Omron CX-Programmer project NuevoProyecto (CX-Programmer 9.50)

# PLC NewPLC1: CQM1 CPU21

## Global symbols (name address type ; comment)
DM0 CHANNEL  ; 0
TIM002 BOOL  ; T2
TIM003 BOOL  ; T3
TIM004 BOOL  ; T4
TIM005 BOOL  ; T5
TIM006 BOOL  ; T6
TIM007 BOOL  ; T7
TIM008 BOOL  ; T8

## Program P10_2 (no task)
Local symbols
EV1 100.04 BOOL  ; EV1=X6·Pm'
EV2 100.05 BOOL  ; EV2=X13·Pm'
EVA 100.00 BOOL  ; EVA=(X1+X10)·Pm'
EVB 100.01 BOOL  ; EVB=(X2+X9)Pm'
EVC 100.02 BOOL  ; EVC=X3·Pm'
EVD 100.03 BOOL  ; EVD=X8·Pm'
Etapa_0 10.00 BOOL
Etapa_1 10.01 BOOL
Etapa_10 10.10 BOOL
Etapa_11 10.11 BOOL
Etapa_12 10.12 BOOL
Etapa_13 10.13 BOOL
Etapa_14 10.14 BOOL
Etapa_2 10.02 BOOL
Etapa_3 10.03 BOOL
Etapa_4 10.04 BOOL
Etapa_5 10.05 BOOL
Etapa_6 10.06 BOOL
Etapa_7 10.07 BOOL
Etapa_8 10.08 BOOL
Etapa_9 10.09 BOOL
FC1 0.04 BOOL  ; Final carrera 1 (CNA)
FC2 0.05 BOOL  ; Final carrera 2 (CNA)
FC3 0.06 BOOL  ; Final carrera 3 (CNA)
FC4 0.07 BOOL  ; Final carrera 4 (CNA)
KCD 100.06 BOOL  ; KCD=(X1+X2+X3+X4)·Pm'
KCI 100.07 BOOL  ; KCI=(X8+X9+X10+X11)·Pm'
KV1D 101.00 BOOL  ; KV1D=X5·Pm'
KV1I 101.01 BOOL  ; KV1I=X7·Pm'
KV2D 101.02 BOOL  ; KV2D=X14·Pm'
KV2I 101.03 BOOL  ; KV2I=X12·Pm'
P 0.02 BOOL  ; Pulsador de paro (CNC)
Pm 15.00 BOOL  ; Pm=P·X0'+Pm·R'
R 0.03 BOOL  ; Pulsador de rearme (CNA)
m1 0.00 BOOL  ; Pulsador de marcha mezcla 1 (CNA)
m2 0.01 BOOL  ; Pulsador de marcha mezcla 2 (CNA)

### Section Sección1_Etapa_0

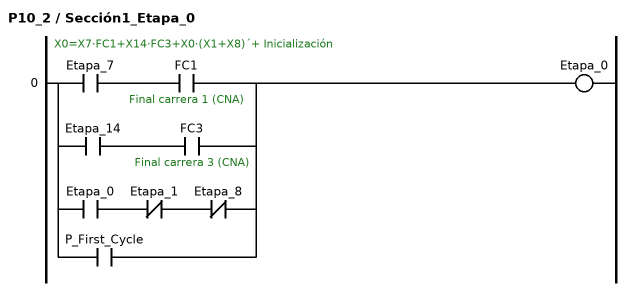
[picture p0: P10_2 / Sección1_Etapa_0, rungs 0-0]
; rung 0: X0=X7·FC1+X14·FC3+X0·(X1+X8)´+ Inicialización
LD Etapa_7
AND FC1  ; Final carrera 1 (CNA)
LD Etapa_14
AND FC3  ; Final carrera 3 (CNA)
ORLD
LD Etapa_0
ANDNOT Etapa_1
ANDNOT Etapa_8
ORLD
OR P_First_Cycle
OUT Etapa_0

### Section Sección2_Mezcla_1_Etapas_1_a_7

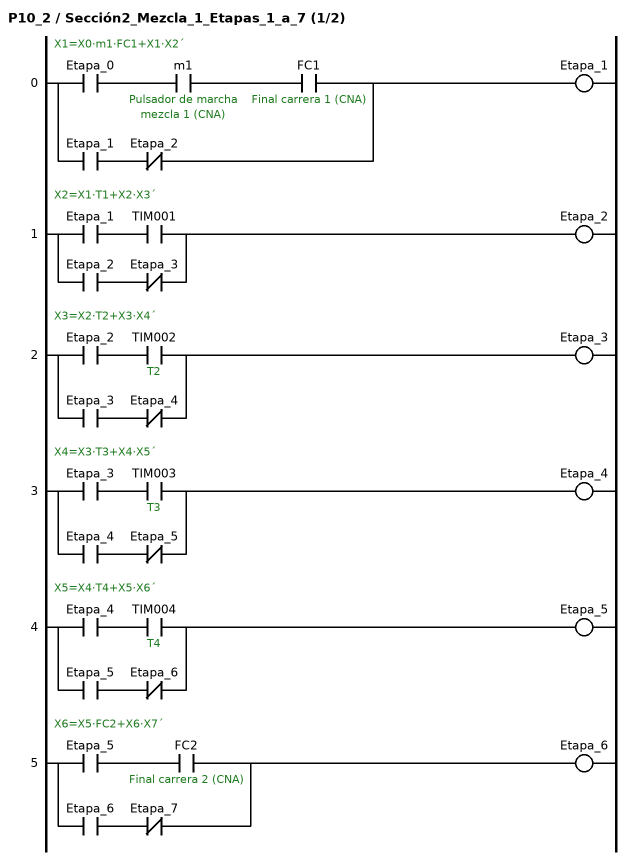
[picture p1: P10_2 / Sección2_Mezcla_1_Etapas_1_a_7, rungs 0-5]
; rung 0: X1=X0·m1·FC1+X1·X2´
LD Etapa_0
AND m1  ; Pulsador de marcha mezcla 1 (CNA)
AND FC1  ; Final carrera 1 (CNA)
LD Etapa_1
ANDNOT Etapa_2
ORLD
OUT Etapa_1
; rung 1: X2=X1·T1+X2·X3´
LD Etapa_1
AND TIM001
LD Etapa_2
ANDNOT Etapa_3
ORLD
OUT Etapa_2
; rung 2: X3=X2·T2+X3·X4´
LD Etapa_2
AND TIM002  ; T2
LD Etapa_3
ANDNOT Etapa_4
ORLD
OUT Etapa_3
; rung 3: X4=X3·T3+X4·X5´
LD Etapa_3
AND TIM003  ; T3
LD Etapa_4
ANDNOT Etapa_5
ORLD
OUT Etapa_4
; rung 4: X5=X4·T4+X5·X6´
LD Etapa_4
AND TIM004  ; T4
LD Etapa_5
ANDNOT Etapa_6
ORLD
OUT Etapa_5
; rung 5: X6=X5·FC2+X6·X7´
LD Etapa_5
AND FC2  ; Final carrera 2 (CNA)
LD Etapa_6
ANDNOT Etapa_7
ORLD
OUT Etapa_6

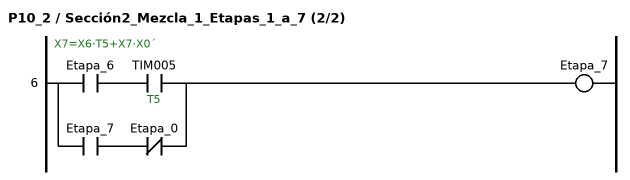
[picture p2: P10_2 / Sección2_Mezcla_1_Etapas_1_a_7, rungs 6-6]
; rung 6: X7=X6·T5+X7·X0´
LD Etapa_6
AND TIM005  ; T5
LD Etapa_7
ANDNOT Etapa_0
ORLD
OUT Etapa_7

### Section Sección3_Mezcla_2_Etapas_8_a_14

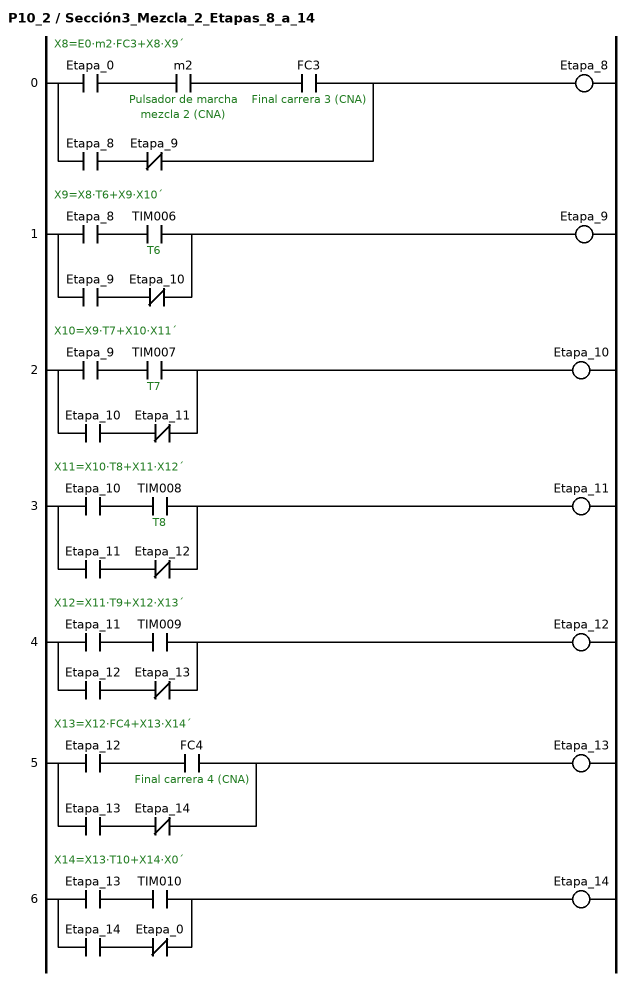
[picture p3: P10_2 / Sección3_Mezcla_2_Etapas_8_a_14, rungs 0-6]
; rung 0: X8=E0·m2·FC3+X8·X9´
LD Etapa_0
AND m2  ; Pulsador de marcha mezcla 2 (CNA)
AND FC3  ; Final carrera 3 (CNA)
LD Etapa_8
ANDNOT Etapa_9
ORLD
OUT Etapa_8
; rung 1: X9=X8·T6+X9·X10´
LD Etapa_8
AND TIM006  ; T6
LD Etapa_9
ANDNOT Etapa_10
ORLD
OUT Etapa_9
; rung 2: X10=X9·T7+X10·X11´
LD Etapa_9
AND TIM007  ; T7
LD Etapa_10
ANDNOT Etapa_11
ORLD
OUT Etapa_10
; rung 3: X11=X10·T8+X11·X12´
LD Etapa_10
AND TIM008  ; T8
LD Etapa_11
ANDNOT Etapa_12
ORLD
OUT Etapa_11
; rung 4: X12=X11·T9+X12·X13´
LD Etapa_11
AND TIM009
LD Etapa_12
ANDNOT Etapa_13
ORLD
OUT Etapa_12
; rung 5: X13=X12·FC4+X13·X14´
LD Etapa_12
AND FC4  ; Final carrera 4 (CNA)
LD Etapa_13
ANDNOT Etapa_14
ORLD
OUT Etapa_13
; rung 6: X14=X13·T10+X14·X0´
LD Etapa_13
AND TIM010
LD Etapa_14
ANDNOT Etapa_0
ORLD
OUT Etapa_14

### Section Sección4_Temporizadores
; Temporizadores

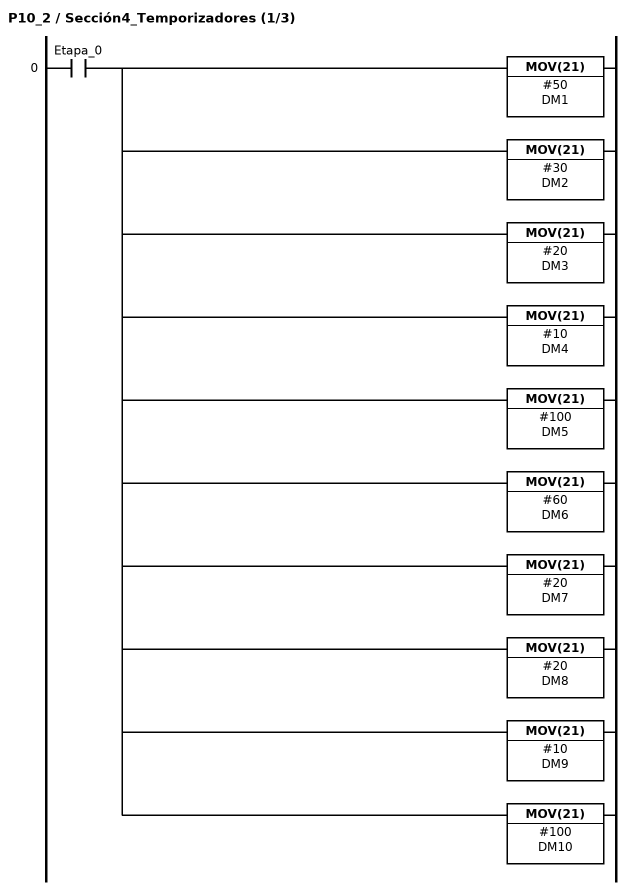
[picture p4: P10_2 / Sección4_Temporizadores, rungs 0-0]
; rung 0
LD Etapa_0
MOV(21) #50 DM1
MOV(21) #30 DM2
MOV(21) #20 DM3
MOV(21) #10 DM4
MOV(21) #100 DM5
MOV(21) #60 DM6
MOV(21) #20 DM7
MOV(21) #20 DM8
MOV(21) #10 DM9
MOV(21) #100 DM10

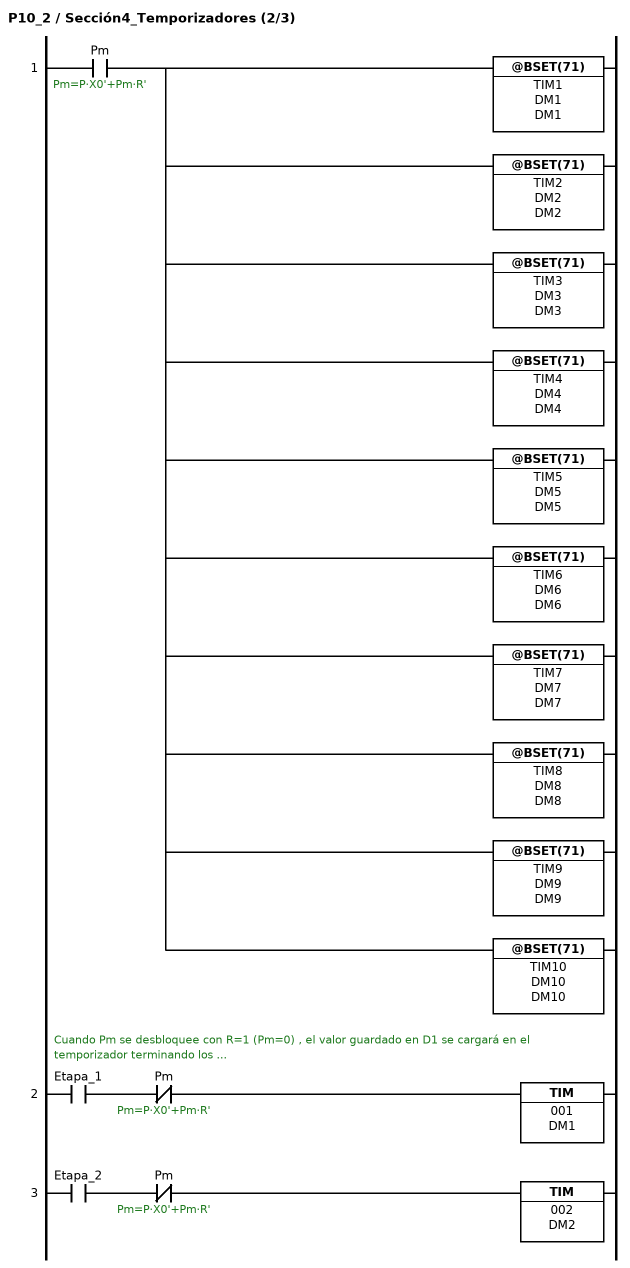
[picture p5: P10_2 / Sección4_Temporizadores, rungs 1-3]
; rung 1
LD Pm  ; Pm=P·X0'+Pm·R'
@BSET(71) TIM1 DM1 DM1  // La instrucción @BSET pasa a D1 el valor que le queda a T1 en el momento de pulsar P (Pm=1)
@BSET(71) TIM2 DM2 DM2
@BSET(71) TIM3 DM3 DM3
@BSET(71) TIM4 DM4 DM4
@BSET(71) TIM5 DM5 DM5
@BSET(71) TIM6 DM6 DM6
@BSET(71) TIM7 DM7 DM7
@BSET(71) TIM8 DM8 DM8
@BSET(71) TIM9 DM9 DM9
@BSET(71) TIM10 DM10 DM10
; rung 2: Cuando Pm se desbloquee con R=1 (Pm=0) , el valor guardado en D1 se cargará en el temporizador terminando los ...
LD Etapa_1
ANDNOT Pm  ; Pm=P·X0'+Pm·R'
TIM 001 DM1  // ... segundos que le quedasen
; rung 3
LD Etapa_2
ANDNOT Pm  ; Pm=P·X0'+Pm·R'
TIM 002 DM2

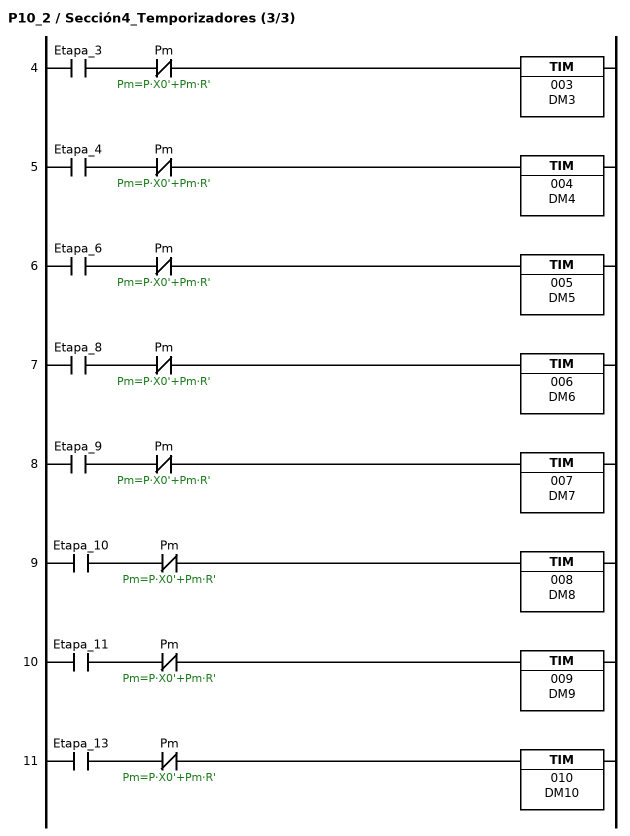
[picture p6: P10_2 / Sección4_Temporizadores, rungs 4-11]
; rung 4
LD Etapa_3
ANDNOT Pm  ; Pm=P·X0'+Pm·R'
TIM 003 DM3
; rung 5
LD Etapa_4
ANDNOT Pm  ; Pm=P·X0'+Pm·R'
TIM 004 DM4
; rung 6
LD Etapa_6
ANDNOT Pm  ; Pm=P·X0'+Pm·R'
TIM 005 DM5
; rung 7
LD Etapa_8
ANDNOT Pm  ; Pm=P·X0'+Pm·R'
TIM 006 DM6
; rung 8
LD Etapa_9
ANDNOT Pm  ; Pm=P·X0'+Pm·R'
TIM 007 DM7
; rung 9
LD Etapa_10
ANDNOT Pm  ; Pm=P·X0'+Pm·R'
TIM 008 DM8
; rung 10
LD Etapa_11
ANDNOT Pm  ; Pm=P·X0'+Pm·R'
TIM 009 DM9
; rung 11
LD Etapa_13
ANDNOT Pm  ; Pm=P·X0'+Pm·R'
TIM 010 DM10

### Section Sección5_Ecuación_Pm

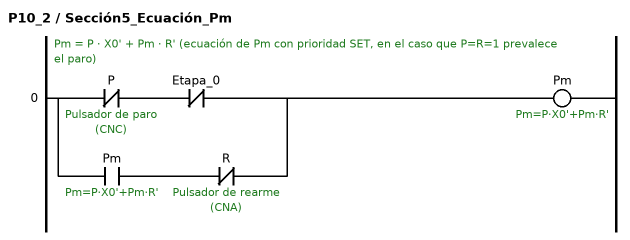
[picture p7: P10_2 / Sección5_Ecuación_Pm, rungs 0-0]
; rung 0: Pm = P · X0' + Pm · R' (ecuación de Pm con prioridad SET, en el caso que P=R=1 prevalece el paro)
LDNOT P  ; Pulsador de paro (CNC)
ANDNOT Etapa_0
LD Pm  ; Pm=P·X0'+Pm·R'
ANDNOT R  ; Pulsador de rearme (CNA)
ORLD
OUT Pm  ; Pm=P·X0'+Pm·R'

### Section Sección6_Salidas
; Salidas

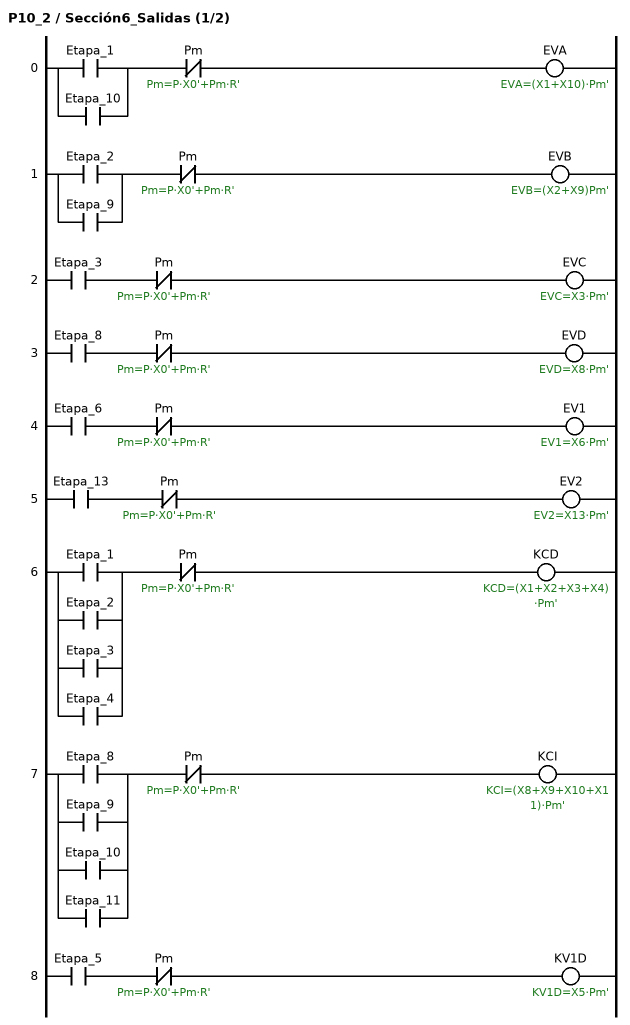
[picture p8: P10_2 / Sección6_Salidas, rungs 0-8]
; rung 0
LD Etapa_1
OR Etapa_10
ANDNOT Pm  ; Pm=P·X0'+Pm·R'
OUT EVA  ; EVA=(X1+X10)·Pm'
; rung 1
LD Etapa_2
OR Etapa_9
ANDNOT Pm  ; Pm=P·X0'+Pm·R'
OUT EVB  ; EVB=(X2+X9)Pm'
; rung 2
LD Etapa_3
ANDNOT Pm  ; Pm=P·X0'+Pm·R'
OUT EVC  ; EVC=X3·Pm'
; rung 3
LD Etapa_8
ANDNOT Pm  ; Pm=P·X0'+Pm·R'
OUT EVD  ; EVD=X8·Pm'
; rung 4
LD Etapa_6
ANDNOT Pm  ; Pm=P·X0'+Pm·R'
OUT EV1  ; EV1=X6·Pm'
; rung 5
LD Etapa_13
ANDNOT Pm  ; Pm=P·X0'+Pm·R'
OUT EV2  ; EV2=X13·Pm'
; rung 6
LD Etapa_1
OR Etapa_2
OR Etapa_3
OR Etapa_4
ANDNOT Pm  ; Pm=P·X0'+Pm·R'
OUT KCD  ; KCD=(X1+X2+X3+X4)·Pm'
; rung 7
LD Etapa_8
OR Etapa_9
OR Etapa_10
OR Etapa_11
ANDNOT Pm  ; Pm=P·X0'+Pm·R'
OUT KCI  ; KCI=(X8+X9+X10+X11)·Pm'
; rung 8
LD Etapa_5
ANDNOT Pm  ; Pm=P·X0'+Pm·R'
OUT KV1D  ; KV1D=X5·Pm'

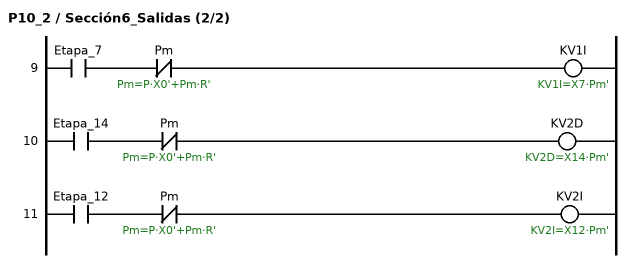
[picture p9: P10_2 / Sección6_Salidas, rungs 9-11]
; rung 9
LD Etapa_7
ANDNOT Pm  ; Pm=P·X0'+Pm·R'
OUT KV1I  ; KV1I=X7·Pm'
; rung 10
LD Etapa_14
ANDNOT Pm  ; Pm=P·X0'+Pm·R'
OUT KV2D  ; KV2D=X14·Pm'
; rung 11
LD Etapa_12
ANDNOT Pm  ; Pm=P·X0'+Pm·R'
OUT KV2I  ; KV2I=X12·Pm'

### Section Sección7_END
; END
; rung 0
END(01)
